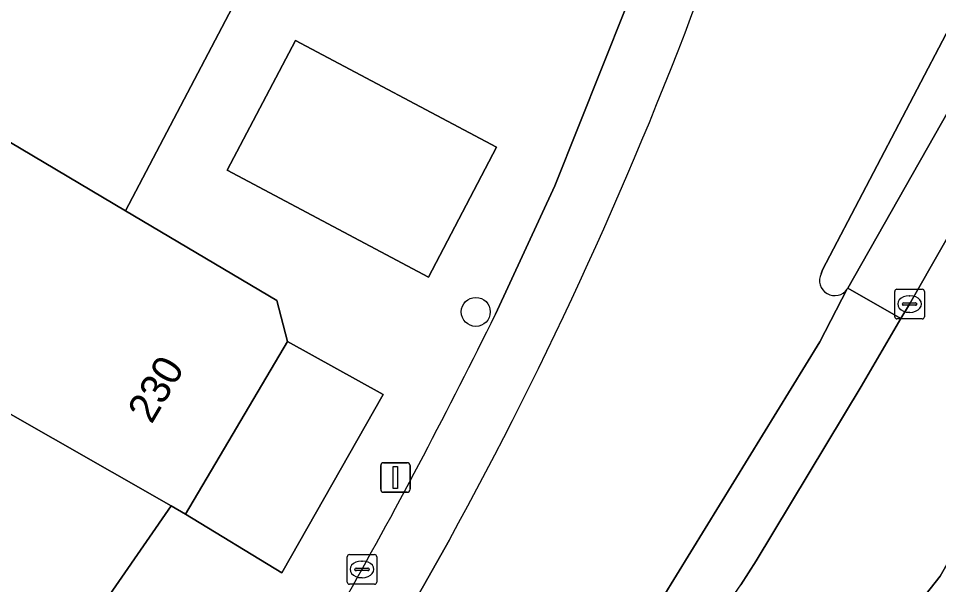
# Model space of a CAD drawing. Extents: x 160157 to 160921, y 381516 to 382045.
# Drawn here: x 160613.86 to 160644.94, y 381846.52 to 381865.63 of the extents above; entities that cross this region are included whole.
import ezdxf

# ---------------------------------------------------------------- set-up
doc = ezdxf.new("R2010")
doc.units = 0
for name, color, linetype in [('IMGEO_Boom', 7, 'Continuous'), ('IMGEO_Erf', 7, 'Continuous'), ('IMGEO_Fietspad_open', 7, 'Continuous'), ('IMGEO_Kolk', 7, 'Continuous'), ('IMGEO_Lichtmast', 7, 'Continuous'), ('IMGEO_Pand', 7, 'Continuous'), ('IMGEO_Pand_nummerreeks', 7, 'Continuous'), ('IMGEO_Parkeervlak_open', 7, 'Continuous'), ('IMGEO_Rijbaan_lokaal_gesloten', 7, 'Continuous'), ('IMGEO_Rijbaan_lokaal_open', 7, 'Continuous'), ('IMGEO_Verkeerseiland_gesloten', 7, 'Continuous'), ('IMGEO_Voetpad_open', 7, 'Continuous')]:
    doc.layers.add(name, color=color, linetype=linetype)

msp = doc.modelspace()

# ---------------------------------------------------------------- linework, layer by layer
at = {"layer": 'IMGEO_Boom'}
msp.add_circle((160629.308, 381855.728), 0.489, dxfattribs=at)
at = {"layer": 'IMGEO_Erf'}
for points in [[(160586.581, 381869.944), (160597.132, 381861.291), (160600.911, 381865.899), (160603.363, 381863.888), (160601.281, 381859.829), (160601.388, 381859.766), (160607.571, 381856.116), (160609.399, 381859.213), (160604.983, 381861.82), (160607.035, 381865.295), (160613.173, 381861.69), (160617.475, 381859.142), (160628.641, 381880.394), (160629.203, 381881.464), (160622.598, 381884.85), (160607.535, 381893.268), (160610.258, 381898.175), (160609.57, 381898.502), (160602.457, 381901.998), (160597.276, 381904.471), (160556.62, 381924.645)], [(160662.715, 381866.57), (160660.296, 381866.624), (160658.571, 381866.17), (160657.082, 381865.462), (160655.682, 381864.592), (160655.188, 381864.027), (160654.415, 381863.144), (160653.212, 381861.298), (160647.699, 381851.584), (160644.987, 381846.807), (160615.493, 381809.458)]]:
    msp.add_lwpolyline(points, dxfattribs=at)
msp.add_lwpolyline([(160626.183, 381852.944), (160622.949, 381854.734), (160619.505, 381848.899), (160622.758, 381846.92)], close=True, dxfattribs=at)
at = {"layer": 'IMGEO_Fietspad_open'}
msp.add_lwpolyline([(160653, 381876.101), (160652.848, 381875.756), (160649.692, 381870.271), (160648.195, 381867.674), (160641.866, 381856.528), (160643.662, 381855.505), (160643.955, 381855.993), (160648.639, 381864.194), (160653.156, 381872.105), (160653.838, 381873.223)], dxfattribs=at)
at = {"layer": 'IMGEO_Kolk'}
for p, q in [((160643.454, 381855.567), (160643.454, 381856.419)), ((160643.529, 381856.493), (160644.381, 381856.493)), ((160643.942, 381856.273), (160643.967, 381856.273)), ((160644.455, 381856.419), (160644.455, 381855.567)), ((160643.713, 381855.987), (160643.713, 381855.999)), ((160644.151, 381855.95), (160643.753, 381855.95)), ((160643.756, 381856.036), (160644.154, 381856.036)), ((160644.197, 381855.999), (160644.197, 381855.987)), ((160643.965, 381855.713), (160643.94, 381855.713)), ((160644.381, 381855.493), (160643.529, 381855.493)), ((160625.039, 381847.537), (160625.891, 381847.537)), ((160624.964, 381846.611), (160624.964, 381847.463)), ((160625.452, 381847.317), (160625.477, 381847.317)), ((160625.965, 381847.463), (160625.965, 381846.611)), ((160625.223, 381847.031), (160625.223, 381847.043)), ((160625.661, 381846.994), (160625.263, 381846.994)), ((160625.266, 381847.08), (160625.664, 381847.08)), ((160625.707, 381847.043), (160625.707, 381847.031)), ((160625.475, 381846.757), (160625.45, 381846.757)), ((160625.891, 381846.537), (160625.039, 381846.537))]:
    msp.add_line(p, q, dxfattribs=at)
for points in [[(160643.454, 381855.567), (160643.454, 381856.419)], [(160643.529, 381856.493), (160644.381, 381856.493)], [(160644.455, 381856.419), (160644.455, 381855.567)], [(160644.381, 381855.493), (160643.529, 381855.493)], [(160625.039, 381847.537), (160625.891, 381847.537)], [(160624.964, 381846.611), (160624.964, 381847.463)], [(160625.965, 381847.463), (160625.965, 381846.611)], [(160625.891, 381846.537), (160625.039, 381846.537)]]:
    msp.add_lwpolyline(points, dxfattribs=at)
for centre, radius, start, end in [((160643.531, 381856.417), 0.0765, 91.552, 178.448), ((160643.531, 381856.417), 0.0765, 91.552, 178.448), ((160644.379, 381856.417), 0.0765, 1.552, 88.448), ((160644.379, 381856.417), 0.0765, 1.552, 88.448), ((160643.753, 381855.996), 0.0403, 85.8775, 175.7526), ((160643.75, 381855.986), 0.0366, 178.938, 274.7102), ((160644.154, 381855.993), 0.043, 264.8664, 352.4533), ((160644.158, 381855.998), 0.0386, 1.7309, 96.639), ((160643.531, 381855.569), 0.0765, 181.552, 268.448), ((160643.531, 381855.569), 0.0765, 181.552, 268.448), ((160644.379, 381855.569), 0.0765, 271.552, 358.448), ((160644.379, 381855.569), 0.0765, 271.552, 358.448), ((160625.041, 381847.461), 0.0765, 91.552, 178.448), ((160625.041, 381847.461), 0.0765, 91.552, 178.448), ((160625.889, 381847.461), 0.0765, 1.552, 88.448), ((160625.889, 381847.461), 0.0765, 1.552, 88.448), ((160625.263, 381847.04), 0.0403, 85.8775, 175.7526), ((160625.26, 381847.03), 0.0366, 178.938, 274.7102), ((160625.664, 381847.037), 0.043, 264.8664, 352.4533), ((160625.668, 381847.042), 0.0386, 1.7309, 96.639), ((160625.041, 381846.613), 0.0765, 181.552, 268.448), ((160625.041, 381846.613), 0.0765, 181.552, 268.448), ((160625.889, 381846.613), 0.0765, 271.552, 358.448), ((160625.889, 381846.613), 0.0765, 271.552, 358.448)]:
    msp.add_arc(centre, radius, start, end, dxfattribs=at)
for centre, major_axis, ratio, start_param, end_param in [((160643.941, 381855.993), (-0.387, 0.002), 0.722429, 4.712389, 7.853982), ((160643.966, 381855.993), (-0.39, 0.002), 0.717154, 1.570796, 4.712389), ((160625.451, 381847.037), (-0.387, 0.002), 0.722429, 4.712389, 7.853982), ((160625.476, 381847.037), (-0.39, 0.002), 0.717154, 1.570796, 4.712389)]:
    msp.add_ellipse(centre, major_axis=major_axis, ratio=ratio, start_param=start_param, end_param=end_param, dxfattribs=at)
at = {"layer": 'IMGEO_Lichtmast'}
for p, q in [((160626.197, 381850.639), (160626.987, 381850.639)), ((160626.987, 381850.639), (160626.197, 381850.639)), ((160626.097, 381849.739), (160626.097, 381850.539)), ((160626.097, 381850.539), (160626.097, 381849.739)), ((160627.087, 381850.539), (160627.087, 381849.739)), ((160627.087, 381849.739), (160627.087, 381850.539)), ((160626.987, 381849.639), (160626.197, 381849.639)), ((160626.197, 381849.639), (160626.987, 381849.639))]:
    msp.add_line(p, q, dxfattribs=at)
msp.add_lwpolyline([(160626.517, 381850.514), (160626.667, 381850.514), (160626.667, 381849.764), (160626.517, 381849.764), (160626.517, 381850.514)], dxfattribs=at)
for centre, start, end in [((160626.197, 381850.539), 90, 180), ((160626.197, 381850.539), 90, 180), ((160626.987, 381850.539), 0, 90), ((160626.987, 381850.539), 360, 90), ((160626.197, 381849.739), 180, 270), ((160626.197, 381849.739), 180, 270), ((160626.987, 381849.739), 270, 0), ((160626.987, 381849.739), 270, 0)]:
    msp.add_arc(centre, 0.1, start, end, dxfattribs=at)
at = {"layer": 'IMGEO_Pand'}
for points in [[(160619.02, 381849.186), (160619.505, 381848.899), (160622.949, 381854.734), (160622.595, 381856.109), (160617.475, 381859.142), (160613.173, 381861.69), (160607.035, 381865.295), (160604.983, 381861.82), (160609.399, 381859.213), (160607.571, 381856.116), (160601.388, 381859.766), (160601.155, 381859.363)], [(160619.02, 381849.186), (160601.155, 381859.363), (160588.491, 381842.842), (160605.3, 381829.37)]]:
    msp.add_lwpolyline(points, close=True, dxfattribs=at)
at = {"layer": 'IMGEO_Parkeervlak_open'}
msp.add_lwpolyline([(160623.22, 381864.893), (160620.909, 381860.517), (160627.716, 381856.906), (160630.007, 381861.294)], close=True, dxfattribs=at)
at = {"layer": 'IMGEO_Rijbaan_lokaal_gesloten'}
msp.add_lwpolyline([(160634.363, 381840.886), (160638.255, 381846.511), (160638.774, 381847.331), (160642.317, 381853.209), (160643.662, 381855.505), (160641.866, 381856.528), (160641.849, 381856.501), (160640.924, 381854.723), (160633.663, 381842.9), (160631.565, 381839.849), (160629.021, 381836.504), (160622.418, 381827.913), (160614.68, 381818.128), (160606.724, 381808.255), (160607.794, 381807.361), (160610.953, 381811.147), (160611.342, 381811.635), (160614.195, 381815.222), (160614.85, 381816.044), (160620.664, 381823.358)], close=True, dxfattribs=at)
at = {"layer": 'IMGEO_Rijbaan_lokaal_open'}
for points in [[(160640.968, 381857.017), (160641.01, 381857.152), (160646.912, 381868.406), (160648.273, 381871.012), (160650.162, 381874.637)], [(160637.101, 381867.271), (160635.017, 381867.981), (160634.372, 381865.993), (160631.978, 381859.981), (160629.976, 381855.653)], [(160608.386, 381818.048), (160603.102, 381811.204), (160606.724, 381808.255), (160614.68, 381818.128), (160622.418, 381827.913), (160629.021, 381836.504), (160631.565, 381839.849), (160633.663, 381842.9), (160640.924, 381854.723), (160641.849, 381856.501)], [(160628.416, 381848.034), (160626.614, 381844.846), (160621.517, 381836.714)], [(160624.978, 381846.161), (160624.799, 381845.862), (160626.614, 381844.846), (160628.416, 381848.034)]]:
    msp.add_lwpolyline(points, dxfattribs=at)
for centre, radius, start, end in [((160505.827, 381915.432), 139.895, 331.19852, 339.7369), ((160505.827, 381915.432), 139.895, 331.19852, 339.7369), ((160641.426, 381856.788), 0.512, 153.4284, 325.8567), ((160448.54, 381945.126), 202.297, 330.71169, 333.75033)]:
    msp.add_arc(centre, radius, start, end, dxfattribs=at)
at = {"layer": 'IMGEO_Verkeerseiland_gesloten'}
for points in [[(160648.195, 381867.674), (160646.912, 381868.406), (160641.01, 381857.152), (160640.968, 381857.017)], [(160641.849, 381856.501), (160641.866, 381856.528), (160648.195, 381867.674)]]:
    msp.add_lwpolyline(points, dxfattribs=at)
msp.add_arc((160641.426, 381856.788), 0.512, 153.4284, 325.8567, dxfattribs=at)
at = {"layer": 'IMGEO_Voetpad_open'}
for points in [[(160636.204, 381887.952), (160632.445, 381887.634), (160629.203, 381881.464), (160628.641, 381880.394), (160617.475, 381859.142), (160622.595, 381856.109), (160622.949, 381854.734), (160626.183, 381852.944), (160622.758, 381846.92), (160619.505, 381848.899), (160619.02, 381849.186), (160605.3, 381829.37), (160603.624, 381826.949), (160587.941, 381807.827), (160580.593, 381798.887)], [(160629.976, 381855.653), (160631.978, 381859.981), (160634.372, 381865.993), (160635.017, 381867.981), (160636.009, 381871.036), (160638.567, 381880.037), (160638.867, 381880.987)], [(160614.597, 381808.384), (160615.388, 381809.332), (160615.493, 381809.458), (160644.987, 381846.807), (160647.699, 381851.584), (160653.212, 381861.298), (160654.415, 381863.144), (160655.188, 381864.027), (160655.682, 381864.592), (160657.082, 381865.462), (160658.571, 381866.17), (160660.296, 381866.624), (160662.715, 381866.57), (160664.857, 381866.115), (160653.156, 381872.105), (160648.639, 381864.194), (160643.955, 381855.993), (160643.662, 381855.505), (160642.317, 381853.209), (160638.774, 381847.331), (160638.255, 381846.511)]]:
    msp.add_lwpolyline(points, dxfattribs=at)
msp.add_lwpolyline([(160623.22, 381864.893), (160630.007, 381861.294), (160627.716, 381856.906), (160620.909, 381860.517)], close=True, dxfattribs=at)
msp.add_arc((160448.54, 381945.126), 202.297, 330.71169, 333.75033, dxfattribs=at)

# ---------------------------------------------------------------- texts
at = {"layer": 'IMGEO_Pand_nummerreeks'}
msp.add_text('230', height=1, rotation=59.4496, dxfattribs=at).set_placement((160618.359, 381851.914))

doc.saveas('drawing.dxf')
